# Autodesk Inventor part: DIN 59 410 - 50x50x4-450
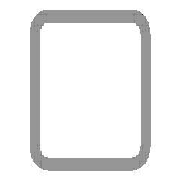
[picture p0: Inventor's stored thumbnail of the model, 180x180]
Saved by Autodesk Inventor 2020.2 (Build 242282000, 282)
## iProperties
Manager: www.cadconsulting.pl
Company: Fabian Stasiak CAD Consulting
Created: 2015-01
Part Number: DIN 59 410 - 50x50x4-450
Material: Stal, miękka
Description: Rurki stalowe o przekroju kwadratowym formowane na gorąco
Document SubType Name: Modellieren
Standard: DIN
Designer: F.Stasiak
Standards Organization: DIN
Language: pl-PL
Size Designation: 50x50x4
Categories: <MemberInstance><Categories><Category DisplayName="Kształtowniki konstrukcyjne" InternalName="089c4875-fa83-4c05-b084-43b9cc11f5ed" Mnemonic="GRDR"><CategoryPar
Stock Number: 50x50x4
Density: 7.85 g/cm^3
Appearance: Częściowo polerowana
Mass: 2508.91 g
Surface Area: 1611.93 cm^2
Volume: 319.606 cm^3
Catalog Web Link: www.expertbooks.pl
_CCFamilyMember: 40
_CCFamilyDisplayName: DIN 59410 (Kwadrat) - Rurki stalowe o przekroju kwadratowym formowane na gorąco
_FrameMemberDoc: Frame Member File
_Version: 15.0.0
_GetPNFromCC: 1
G_W: 50,000 mm
G_H: 50,000 mm
G_L: 450,000 mm
+7909C591-DBA7-4174-9E9C-0D705C2ECB23+CUTDETAIL3: Wytnij
+38B810BE-5A5C-4084-A45F-E12965C5F561+CUTDETAIL4: Wytnij
IsCustomPart: 1
Author: F.Stasiak
Subject: Zbiór ćwiczeń. Autodesk Inventor 2020. Kurs Professional
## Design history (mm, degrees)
node "Płaszczyzna początkowa"
node "Płaszczyzna końcowa"
sketch "Szkic"
  geometry: L1 (-17, 25)-(17, 25); L2 (25, 17)-(25, -17); L3 (17, -25)-(-17, -25); L4 (-25, -17)-(-25, 17); L5 (-37.32, 0)-(37.32, 0) reference; L6 (0, -37.32)-(0, 37.32) reference; L7 (-17, 21)-(17, 21); L8 (21, 17)-(21, -17); L9 (17, -21)-(-17, -21); L10 (-21, -17)-(-21, 17); A1 r 8 centre (-17, 17) between (-17, 25) and (-25, 17); A2 r 8 centre (17, 17) between (25, 17) and (17, 25); A3 r 8 centre (17, -17) between (17, -25) and (25, -17); A4 r 8 centre (-17, -17) between (-25, -17) and (-17, -25); A5 r 4 centre (-17, 17) between (-17, 21) and (-21, 17); A6 r 4 centre (17, 17) between (21, 17) and (17, 21); A7 r 4 centre (17, -17) between (17, -21) and (21, -17); A8 r 4 centre (-17, -17) between (-21, -17) and (-17, -21); 3 further points
  constraints: 16 end point, 16 point on circle, 8 centre point, 8 tangent, 6 point on line, 4 parallel, 3 equal radius, 3 perpendicular, 1 horizontal, 7 other
  dimensions: "b" = 50 distance of point (-25, 25) point (25, 25); "msp_r" = 8 radius of A1 (= 2 x ParT); "d8" = 25 distance between parallel lines of L4 L6 (= d9); "d9" = 25 distance between parallel lines of L3 L5 (= 0.5 x b); "d10" = 4 distance between parallel lines of L3 L9 (= ParT)
extrude "Bryła" new body sketch "Szkic" taper "d4" = 0 deg; stored distance "NLG" = 10
node "Driven Length"
  sketch "Sketch2"
    geometry: L1 (0, 0)-(10, 0) reference
    constraints: 2 end point, 1 horizontal
  workplane "Work Plane3"
  sketch "Sketch3"
    geometry: L1 (-2, -25)-(12, -25) reference; L2 (-2, 425)-(12, 425) reference
    dimensions: "d14" = 450 distance between parallel lines of L1 L2 (derived)
node "Płaszczyzna konstrukcyjna6"
feature "Podział3"
node "Płaszczyzna konstrukcyjna7"
feature "Podział4"
body "Solid1"
other parameters: "ParT" = 4, "G_OFFSET_START" = 25 [user parameter; used in 1 equation term], "G_OFFSET_END" = -25 [user parameter; used in 1 equation term], "d11" = -25 (= -G_OFFSET_START), "d12" = 425 (= G_OFFSET_END + B_L), "G_L" = 450 (= d14) [user parameter], "d13" = 90 deg
